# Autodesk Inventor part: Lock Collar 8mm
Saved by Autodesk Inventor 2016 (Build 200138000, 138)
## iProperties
Created: 2016-01
Part Number: Lock Collar 8mm
Material: Generic
Document SubType Name: Modeling
Designer: John
Density: 1 g/cm^3
Appearance: Default
Author: John
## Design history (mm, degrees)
feature "M5X0.8 TAPPED HOLE1"
body "Solid1"
